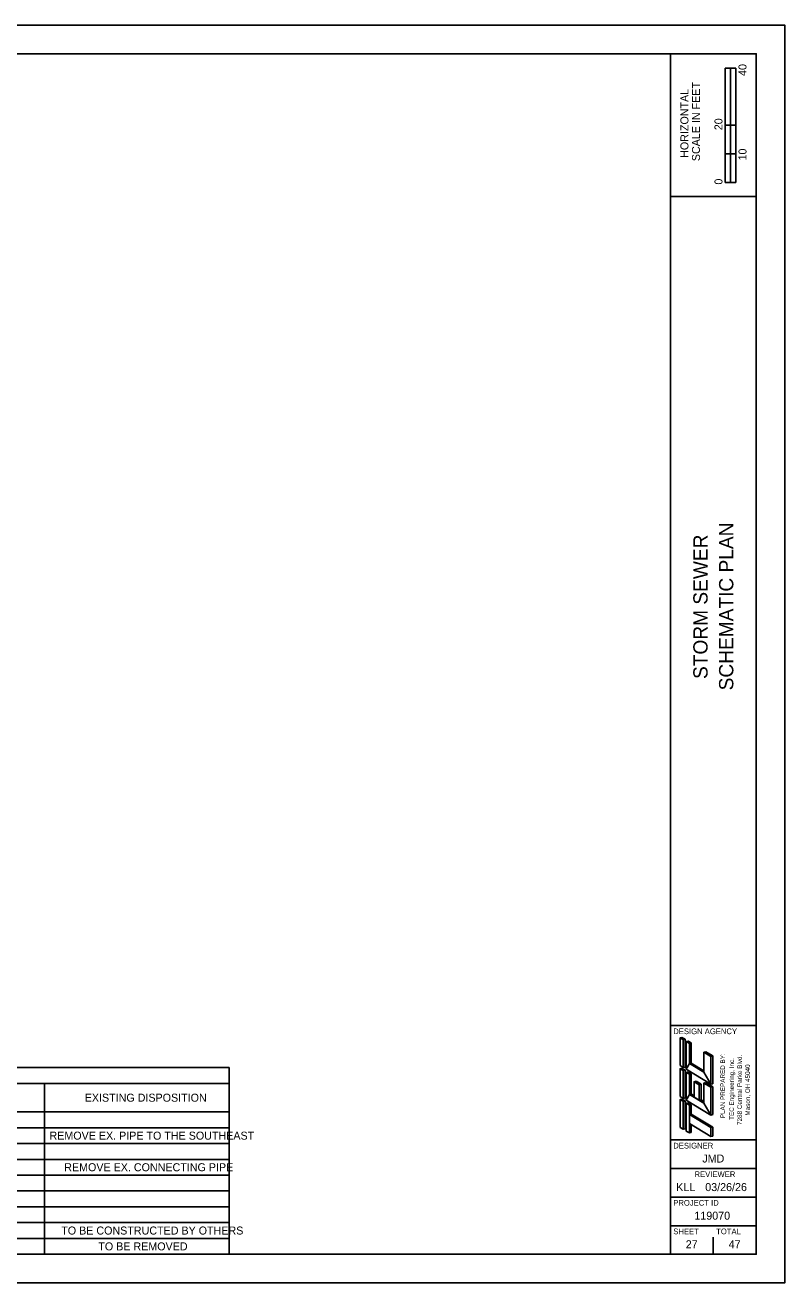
# Model space of a CAD drawing. Extents: x -1.5 to 34, y 0 to 22.
# Drawn here: x 20.72 to 34, y 0 to 22 of the extents above; entities that cross this region are included whole.
import ezdxf

# ---------------------------------------------------------------- set-up
doc = ezdxf.new("R2010")
doc.units = 0
for name, color, linetype in [('Default', 7, 'Continuous'), ('PF_P_Sta_Elev_Text', 7, 'Continuous'), ('SH_Border', 7, 'Continuous'), ('SH_Cut_Line', 7, 'Continuous'), ('SH_Data', 7, 'Continuous'), ('SH_Text', 7, 'Continuous')]:
    doc.layers.add(name, color=color, linetype=linetype)

msp = doc.modelspace()

# ---------------------------------------------------------------- linework, layer by layer
at = {"layer": 'PF_P_Sta_Elev_Text'}
for p, q in [((1.5, 3.765), (24.285, 3.765)), ((24.285, 3.765), (24.285, 0.5)), ((1.5, 3.488), (24.285, 3.488)), ((21.061, 3.488), (21.061, 0.5)), ((1.5, 2.99), (24.285, 2.99)), ((1.5, 2.713), (24.285, 2.713)), ((1.5, 2.437), (24.285, 2.437)), ((1.5, 2.16), (24.285, 2.16)), ((1.5, 1.883), (24.285, 1.883)), ((1.5, 1.607), (24.285, 1.607)), ((1.5, 1.33), (24.285, 1.33)), ((1.5, 1.053), (24.285, 1.053)), ((1.5, 0.777), (24.285, 0.777)), ((1.5, 0.5), (24.285, 0.5))]:
    msp.add_line(p, q, dxfattribs=at)
at = {"layer": 'SH_Border'}
for p, q in [((32, 0.5), (32, 21.5)), ((32, 19), (33.5, 19)), ((32, 4.5), (33.5, 4.5)), ((32, 2.5), (33.5, 2.5)), ((32, 2), (33.5, 2)), ((32, 1.5), (33.5, 1.5)), ((32, 1), (33.5, 1))]:
    msp.add_line(p, q, dxfattribs=at)
msp.add_lwpolyline([(1.5, 21.5), (33.5, 21.5), (33.5, 0.5), (1.5, 0.5)], close=True, dxfattribs=at)
at = {"layer": 'SH_Cut_Line'}
msp.add_lwpolyline([(0, 0), (34, 0), (34, 22), (0, 22)], close=True, dxfattribs=at)
at = {"layer": 'SH_Data'}
for p, q in [((32.957, 19.25), (32.957, 21.25)), ((33.144, 21.25), (32.957, 21.25)), ((32.957, 20.25), (32.957, 21.25)), ((32.957, 21.25), (33.05, 21.25)), ((33.05, 21.25), (33.051, 21.25)), ((33.051, 21.25), (33.051, 20.25)), ((33.144, 21.25), (33.144, 19.25)), ((33.051, 20.25), (32.957, 20.25)), ((33.143, 20.25), (33.05, 20.25)), ((33.05, 20.25), (33.05, 19.75)), ((33.143, 19.75), (33.143, 20.25)), ((33.05, 19.75), (32.957, 19.75)), ((32.957, 19.75), (32.957, 19.25)), ((33.05, 19.25), (33.05, 19.75)), ((33.05, 19.75), (33.143, 19.75)), ((33.144, 19.25), (32.957, 19.25)), ((32.957, 19.25), (33.05, 19.25)), ((32.75, 3.5), (32.75, 3.5)), ((32.375, 0.675), (32.375, 0.675)), ((32.75, 0.5), (32.75, 0.8))]:
    msp.add_line(p, q, dxfattribs=at)
at = {"layer": 'SH_Text'}
for p, q in [((32.169, 4.285), (32.201, 4.294)), ((32.169, 3.799), (32.169, 4.285)), ((32.223, 4.253), (32.169, 4.285)), ((32.255, 4.261), (32.201, 4.294)), ((32.223, 4.253), (32.255, 4.261)), ((32.223, 3.767), (32.223, 4.253)), ((32.255, 3.775), (32.255, 4.261)), ((32.277, 4.221), (32.309, 4.229)), ((32.331, 4.188), (32.277, 4.221)), ((32.277, 3.735), (32.277, 4.221)), ((32.309, 4.229), (32.363, 4.196)), ((32.331, 4.188), (32.363, 4.196)), ((32.331, 3.837), (32.331, 4.188)), ((32.363, 4.196), (32.363, 3.845)), ((32.587, 4.034), (32.62, 4.042)), ((32.587, 3.683), (32.587, 4.034)), ((32.709, 3.961), (32.587, 4.034)), ((32.62, 4.042), (32.741, 3.97)), ((32.709, 3.961), (32.741, 3.97)), ((32.709, 3.475), (32.709, 3.961)), ((32.741, 3.97), (32.741, 3.484)), ((32.223, 3.767), (32.169, 3.799)), ((32.169, 3.745), (32.201, 3.754)), ((32.169, 3.259), (32.169, 3.745)), ((32.223, 3.713), (32.169, 3.745)), ((32.255, 3.722), (32.201, 3.754)), ((32.223, 3.767), (32.255, 3.775)), ((32.331, 3.837), (32.363, 3.845)), ((32.587, 3.683), (32.331, 3.837)), ((32.363, 3.845), (32.587, 3.711)), ((32.223, 3.713), (32.255, 3.722)), ((32.223, 3.227), (32.223, 3.713)), ((32.255, 3.236), (32.255, 3.722)), ((32.709, 3.475), (32.277, 3.735)), ((32.277, 3.681), (32.309, 3.689)), ((32.277, 3.195), (32.277, 3.681)), ((32.331, 3.648), (32.277, 3.681)), ((32.309, 3.689), (32.363, 3.656)), ((32.331, 3.648), (32.363, 3.656)), ((32.331, 3.297), (32.331, 3.648)), ((32.363, 3.656), (32.363, 3.305)), ((32.415, 3.519), (32.448, 3.527)), ((32.448, 3.527), (32.535, 3.474)), ((32.331, 3.297), (32.363, 3.305)), ((32.363, 3.305), (32.415, 3.274)), ((32.415, 3.519), (32.415, 3.247)), ((32.415, 3.519), (32.503, 3.466)), ((32.503, 3.466), (32.535, 3.474)), ((32.503, 3.466), (32.503, 3.194)), ((32.535, 3.474), (32.535, 3.202)), ((32.587, 3.494), (32.62, 3.502)), ((32.587, 3.143), (32.587, 3.494)), ((32.709, 3.421), (32.587, 3.494)), ((32.62, 3.502), (32.741, 3.43)), ((32.709, 3.475), (32.741, 3.484)), ((32.709, 3.421), (32.741, 3.43)), ((32.709, 2.935), (32.709, 3.421)), ((32.741, 3.43), (32.741, 2.944)), ((32.223, 3.227), (32.169, 3.259)), ((32.169, 3.205), (32.201, 3.215)), ((32.169, 2.719), (32.169, 3.205)), ((32.223, 3.173), (32.169, 3.205)), ((32.255, 3.181), (32.201, 3.215)), ((32.222, 3.173), (32.255, 3.181)), ((32.223, 3.227), (32.255, 3.236)), ((32.223, 2.687), (32.223, 3.173)), ((32.255, 2.695), (32.255, 3.181)), ((32.709, 2.935), (32.277, 3.195)), ((32.277, 3.141), (32.309, 3.151)), ((32.331, 3.108), (32.277, 3.141)), ((32.277, 2.655), (32.277, 3.141)), ((32.309, 3.151), (32.363, 3.116)), ((32.415, 3.247), (32.331, 3.297)), ((32.331, 3.108), (32.363, 3.116)), ((32.331, 2.944), (32.331, 3.108)), ((32.363, 3.116), (32.363, 2.952)), ((32.503, 3.194), (32.535, 3.202)), ((32.587, 3.143), (32.503, 3.194)), ((32.535, 3.202), (32.587, 3.171)), ((32.331, 2.944), (32.363, 2.952)), ((32.331, 2.944), (32.709, 2.717)), ((32.363, 2.952), (32.741, 2.725)), ((32.709, 2.935), (32.741, 2.944)), ((32.223, 2.687), (32.169, 2.719)), ((32.223, 2.687), (32.255, 2.695)), ((32.331, 2.622), (32.277, 2.655)), ((32.331, 2.787), (32.709, 2.56)), ((32.331, 2.622), (32.331, 2.787)), ((32.363, 2.63), (32.363, 2.767)), ((32.709, 2.717), (32.741, 2.725)), ((32.709, 2.56), (32.709, 2.717)), ((32.741, 2.725), (32.741, 2.568)), ((32.331, 2.622), (32.363, 2.63)), ((32.709, 2.56), (32.741, 2.568))]:
    msp.add_line(p, q, dxfattribs=at)
for points in [[(32.169, 3.799), (32.223, 3.767), (32.223, 4.253), (32.169, 4.285)], [(32.277, 3.735), (32.331, 3.837), (32.331, 4.188), (32.277, 4.221)], [(32.709, 3.475), (32.587, 3.683), (32.587, 4.034), (32.709, 3.961)], [(32.169, 3.259), (32.223, 3.227), (32.223, 3.713), (32.169, 3.745)], [(32.277, 3.735), (32.331, 3.837), (32.587, 3.683), (32.709, 3.475)], [(32.277, 3.195), (32.331, 3.297), (32.331, 3.648), (32.277, 3.681)], [(32.415, 3.247), (32.415, 3.519), (32.503, 3.466), (32.503, 3.194)], [(32.709, 2.935), (32.587, 3.143), (32.587, 3.494), (32.709, 3.421)], [(32.169, 2.719), (32.223, 2.687), (32.223, 3.173), (32.169, 3.205)], [(32.277, 3.195), (32.331, 3.297), (32.587, 3.143), (32.709, 2.935)], [(32.277, 2.655), (32.331, 2.622), (32.331, 3.108), (32.277, 3.141)], [(32.331, 2.787), (32.331, 2.944), (32.709, 2.717), (32.709, 2.56)]]:
    msp.add_lwpolyline(points, close=True, dxfattribs=at)

# ---------------------------------------------------------------- texts
at = {"layer": 'Default'}
for s, p in [('PLAN PREPARED BY:', (32.954, 2.88)), ('TEC Engineering, Inc.', (33.11, 2.851)), ('7288 Central Parke Blvd.', (33.25, 2.762)), ('Mason, OH 45040', (33.39, 2.925))]:
    msp.add_text(s, height=0.08, rotation=90, dxfattribs=at).set_placement(p)
at = {"layer": 'PF_P_Sta_Elev_Text'}
for s, p in [('EXISTING DISPOSITION', (21.762, 3.169)), ('REMOVE EX. PIPE TO THE SOUTHEAST', (21.146, 2.505)), ('REMOVE EX. CONNECTING PIPE', (21.404, 1.952)), ('TO BE CONSTRUCTED BY OTHERS', (21.352, 0.845)), ('TO BE REMOVED', (22, 0.568))]:
    msp.add_text(s, height=0.14, dxfattribs=at).set_placement(p)
at = {"layer": 'SH_Data'}
for s, height, p in [('40', 0.14, (33.33, 21.112)), ('SCALE IN FEET', 0.14, (32.517, 19.621)), ('HORIZONTAL', 0.14, (32.315, 19.679)), ('20', 0.14, (32.91, 20.162)), ('10', 0.14, (33.33, 19.633)), ('0', 0.14, (32.91, 19.211)), ('SCHEMATIC PLAN', 0.25, (33.1, 10.364)), ('STORM SEWER', 0.25, (32.65, 10.563))]:
    msp.add_text(s, height=height, rotation=90, dxfattribs=at).set_placement(p)
for s, height, p in [('DESIGN AGENCY', 0.1, (32.05, 4.35)), ('DESIGNER', 0.1, (32.05, 2.35)), ('JMD', 0.14, (32.558, 2.105)), ('REVIEWER', 0.1, (32.422, 1.85)), ('KLL', 0.14, (32.101, 1.605)), ('03/26/26', 0.14, (32.609, 1.605)), ('PROJECT ID', 0.1, (32.05, 1.35)), ('119070', 0.14, (32.419, 1.105)), ('SHEET', 0.1, (32.05, 0.85)), ('TOTAL', 0.1, (32.8, 0.85)), ('27', 0.14, (32.268, 0.605)), ('47', 0.14, (33.018, 0.605))]:
    msp.add_text(s, height=height, dxfattribs=at).set_placement(p)

doc.saveas('drawing.dxf')
